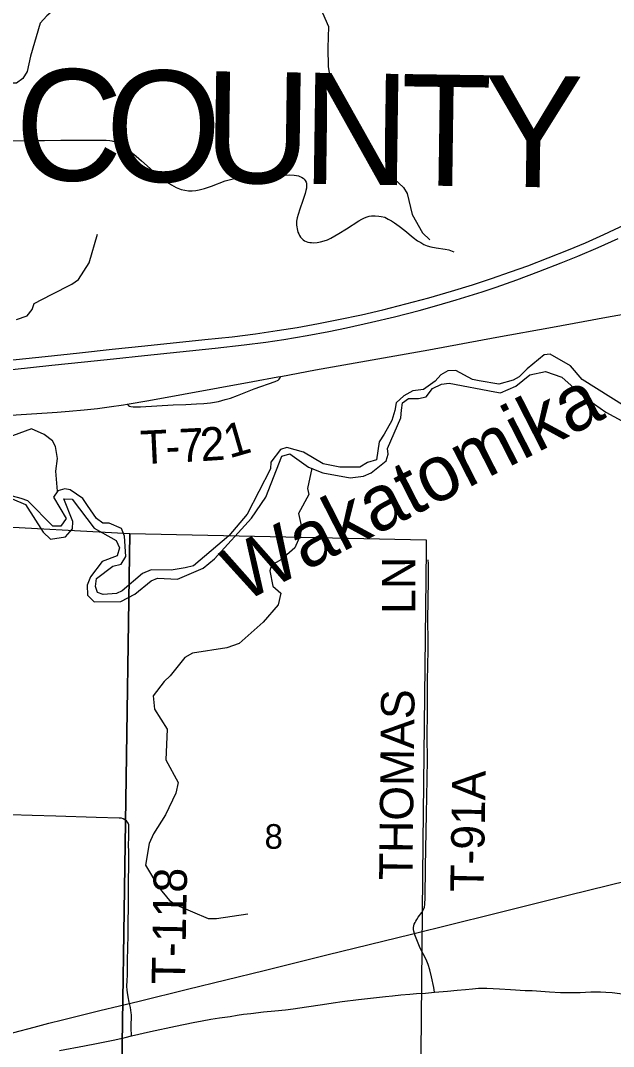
# Model space of a CAD drawing. Extents: x 0 to 34, y 0 to 22.
# Drawn here: x 3.791 to 4.8, y 14.491 to 16.238 of the extents above; entities that cross this region are included whole.
import ezdxf

# ---------------------------------------------------------------- set-up
doc = ezdxf.new("R2010")
doc.units = 0
for name, color, linetype in [('GM_X_Corporation', 7, 'Continuous'), ('GM_X_County_Road', 7, 'Continuous'), ('GM_X_County_Text', 7, 'Continuous'), ('GM_X_Minor_River', 7, 'Continuous'), ('GM_X_Minor_River_Text', 7, 'Continuous'), ('GM_X_Rail_Line', 7, 'Continuous'), ('GM_X_Section_Text', 7, 'Continuous'), ('GM_X_State_Route', 7, 'Continuous'), ('GM_X_Township_Road', 7, 'Continuous'), ('GM_X_Township_Road_Text', 7, 'Continuous')]:
    doc.layers.add(name, color=color, linetype=linetype)

msp = doc.modelspace()

# ---------------------------------------------------------------- linework, layer by layer
at = {"layer": 'GM_X_Corporation'}
for points in [[(2.9706, 15.4194), (3.9769, 15.3648), (3.9619, 14.3814), (2.9463, 14.4019)], [(3.9769, 15.3648), (4.4816, 15.354), (4.4815, 15.3372), (4.4758, 14.8389), (4.4713, 14.3604), (3.9619, 14.3814)]]:
    msp.add_lwpolyline(points, close=True, dxfattribs=at)
at = {"layer": 'GM_X_County_Road'}
for points in [[(4.2337, 15.6322), (4.2931, 15.6431), (4.4857, 15.6775), (4.6018, 15.6992), (4.6966, 15.7158), (4.7485, 15.7255), (4.7882, 15.7329), (4.8463, 15.7434), (4.9165, 15.7564), (4.9688, 15.7656)], [(3.9724, 15.5847), (4.0089, 15.5909), (4.1862, 15.6233), (4.2289, 15.6313), (4.2337, 15.6322)], [(3.3059, 15.4754), (3.3075, 15.4763), (3.3318, 15.49), (3.354, 15.501), (3.3796, 15.5123), (3.4056, 15.5223), (3.4292, 15.53), (3.4531, 15.5365), (3.4653, 15.5394), (3.4813, 15.5428), (3.4944, 15.5453), (3.5078, 15.5475), (3.5356, 15.5508), (3.5699, 15.5534), (3.6591, 15.5589), (3.8362, 15.5703), (3.8532, 15.5715), (3.8734, 15.573), (3.8993, 15.5755), (3.9215, 15.5778), (3.9414, 15.5802), (3.966, 15.5837), (3.9724, 15.5847)], [(4.4957, 14.5837), (4.5177, 14.5854), (4.5343, 14.5869), (4.5484, 14.5883), (4.5601, 14.5896), (4.5703, 14.5904), (4.5849, 14.5905), (4.6065, 14.5894), (4.6251, 14.5883), (4.6498, 14.5868), (4.6619, 14.5864), (4.6916, 14.5843), (4.7103, 14.5834), (4.7239, 14.5831), (4.7363, 14.5834), (4.7437, 14.5834), (4.7618, 14.5843), (4.7783, 14.5843), (4.7875, 14.584), (4.7978, 14.583), (4.8371, 14.5782)], [(3.9795, 14.5092), (4.012, 14.5166), (4.0544, 14.526), (4.0848, 14.532), (4.0998, 14.5348), (4.1147, 14.5377), (4.1296, 14.54), (4.1479, 14.5424), (4.1597, 14.5443), (4.1705, 14.5461), (4.183, 14.5476), (4.2045, 14.55), (4.2237, 14.5518), (4.2417, 14.5538), (4.2549, 14.5555), (4.2775, 14.5585), (4.3051, 14.5628), (4.3233, 14.5657), (4.3384, 14.5678), (4.3661, 14.571), (4.412, 14.5763), (4.4242, 14.5777), (4.4384, 14.5791), (4.4536, 14.5804), (4.4648, 14.5814), (4.4802, 14.5823), (4.4957, 14.5837)], [(3.8571, 14.4846), (3.8999, 14.4925), (3.92, 14.4965), (3.9512, 14.5027), (3.969, 14.5068), (3.9795, 14.5092)]]:
    msp.add_lwpolyline(points, dxfattribs=at)
at = {"layer": 'GM_X_Minor_River'}
for points in [[(3.9737, 16.3586), (3.9672, 16.3431), (3.9366, 16.3195), (3.9114, 16.2986), (3.8574, 16.265), (3.8355, 16.2459), (3.8242, 16.2334), (3.8078, 16.1772), (3.8019, 16.1514), (3.7947, 16.1392), (3.7838, 16.1316), (3.7626, 16.1315), (3.7271, 16.1173), (3.7142, 16.1177), (3.6823, 16.1327)], [(4.3024, 16.3549), (4.2985, 16.3224), (4.2865, 16.2904), (4.2881, 16.2757), (4.3049, 16.2514), (4.3148, 16.228), (4.3138, 16.1919), (4.3143, 16.1593), (4.3198, 16.1293), (4.3541, 16.0631), (4.385, 16.0173), (4.4044, 15.9897), (4.4428, 15.9538), (4.4489, 15.9436), (4.4574, 15.9076), (4.4753, 15.8769), (4.4875, 15.8648)], [(3.784, 15.7291), (3.8021, 15.7356), (3.8104, 15.7459), (3.8142, 15.7561), (3.8432, 15.7718), (3.878, 15.789), (3.8893, 15.797), (3.9074, 15.8255), (3.9215, 15.8741)], [(4.8203, 15.5811), (4.747, 15.6267), (4.7273, 15.6502), (4.6923, 15.6698), (4.6821, 15.669), (4.6535, 15.645), (4.6395, 15.6313), (4.6297, 15.6259), (4.6049, 15.6192), (4.5714, 15.6246), (4.5604, 15.6268), (4.5316, 15.6423), (4.5183, 15.6415), (4.5063, 15.635), (4.4965, 15.6239), (4.4768, 15.6098), (4.4587, 15.6075), (4.4432, 15.5991), (4.4304, 15.5873), (4.4282, 15.574), (4.4231, 15.557), (4.4098, 15.5341), (4.4015, 15.5208), (4.3967, 15.4902), (4.3816, 15.4854), (4.3685, 15.4779), (4.3345, 15.4779), (4.3059, 15.4833), (4.2725, 15.5033), (4.2441, 15.5111), (4.2331, 15.508), (4.2169, 15.486), (4.2162, 15.475), (4.1768, 15.3978), (4.1452, 15.3609), (4.0852, 15.3099), (4.0712, 15.306), (4.047, 15.3021), (4.0129, 15.3031), (3.9982, 15.2966), (3.9639, 15.2673), (3.9541, 15.2623), (3.9314, 15.2607), (3.9215, 15.2641), (3.9181, 15.2743), (3.9199, 15.288), (3.9478, 15.309), (3.9622, 15.3124), (3.9701, 15.3254), (3.968, 15.3599), (3.9627, 15.3731), (3.9418, 15.3822), (3.9308, 15.3825), (3.9202, 15.3904), (3.9046, 15.4124), (3.8966, 15.4245), (3.8753, 15.4392), (3.8659, 15.4407), (3.8541, 15.4376), (3.847, 15.4266), (3.8684, 15.3902), (3.8593, 15.3769), (3.8457, 15.3773), (3.8031, 15.4203), (3.7917, 15.4245), (3.7686, 15.4308)], [(3.7766, 15.4237), (3.7994, 15.4143), (3.8291, 15.367), (3.842, 15.3549), (3.8674, 15.3591), (3.8794, 15.3724), (3.8797, 15.385), (3.8644, 15.424), (3.8784, 15.4229), (3.9161, 15.3737), (3.9533, 15.3526), (3.959, 15.3401), (3.9553, 15.3264), (3.9296, 15.3172), (3.91, 15.291), (3.9044, 15.2769), (3.9049, 15.2599), (3.9159, 15.2485), (3.9617, 15.2487), (3.9851, 15.2613), (4.013, 15.2842), (4.024, 15.2888), (4.0581, 15.287), (4.1015, 15.3054), (4.1207, 15.3217), (4.184, 15.3906), (4.2085, 15.4264), (4.2358, 15.4963), (4.249, 15.5005), (4.2813, 15.4779), (4.3052, 15.4681), (4.3518, 15.4595), (4.3749, 15.4623), (4.3877, 15.468), (4.413, 15.4886), (4.4164, 15.4996), (4.4156, 15.5095), (4.4381, 15.5615), (4.4391, 15.5748), (4.441, 15.5873), (4.4514, 15.5947), (4.4683, 15.5947), (4.4811, 15.5973), (4.4923, 15.6118), (4.5075, 15.619), (4.5207, 15.6206), (4.598, 15.6061), (4.6078, 15.6042), (4.6339, 15.6157), (4.658, 15.6348), (4.6845, 15.6405), (4.7122, 15.6308), (4.7487, 15.5987), (4.787, 15.5715), (4.8345, 15.5458)], [(3.8538, 15.437), (3.8506, 15.471), (3.8539, 15.4922), (3.8504, 15.5127), (3.8451, 15.5226), (3.831, 15.5335), (3.8094, 15.5429), (3.7769, 15.531)], [(4.2866, 15.4757), (4.2791, 15.4416), (4.2818, 15.431), (4.2642, 15.3986), (4.2684, 15.3782), (4.2674, 15.3626), (4.2576, 15.3402), (4.235, 15.3207), (4.218, 15.3108), (4.2154, 15.3013), (4.2204, 15.2748), (4.2341, 15.2631), (4.2293, 15.2433), (4.204, 15.214), (4.1629, 15.1774), (4.1421, 15.1701), (4.0837, 15.1611), (4.0705, 15.1538), (4.0453, 15.1222), (4.0351, 15.1127), (4.0166, 15.0883), (4.019, 15.0656), (4.0404, 15.0315), (4.0383, 14.9796), (4.059, 14.941), (4.0549, 14.9227), (4.0376, 14.8855), (4.0169, 14.8531), (4.0098, 14.8368), (4.0035, 14.8), (4.0261, 14.7617), (4.0444, 14.7398), (4.0569, 14.7319), (4.1104, 14.7094), (4.1241, 14.7091), (4.1779, 14.7173)]]:
    msp.add_lwpolyline(points, dxfattribs=at)
at = {"layer": 'GM_X_Rail_Line'}
msp.add_lwpolyline([(3.6972, 14.4902), (3.7191, 14.4967), (3.74, 14.5034), (3.7793, 14.5148), (3.8138, 14.5243), (3.839, 14.5311), (3.862, 14.5367), (3.9255, 14.5525), (3.9926, 14.5684), (4.075, 14.5889), (4.2057, 14.6209), (4.3124, 14.6473), (4.4566, 14.6827), (4.5938, 14.7167), (4.7232, 14.7487), (4.8596, 14.7823)], dxfattribs=at)
at = {"layer": 'GM_X_State_Route'}
for points in [[(3.7061, 15.653), (3.8327, 15.6663), (3.8914, 15.6724), (3.947, 15.6783), (4.0026, 15.6843), (4.1045, 15.6948), (4.1509, 15.6998), (4.191, 15.7049), (4.2279, 15.7103), (4.2616, 15.7157), (4.2983, 15.7223), (4.3319, 15.7288), (4.3714, 15.7372), (4.4077, 15.7457), (4.4468, 15.7557), (4.4858, 15.7662), (4.5246, 15.7774), (4.5602, 15.7883), (4.5927, 15.7989), (4.6251, 15.81), (4.6542, 15.8207), (4.689, 15.8341), (4.7237, 15.8478), (4.7524, 15.8598), (4.7836, 15.8736), (4.8203, 15.8906)], [(3.7762, 15.6437), (3.8441, 15.6511), (3.8997, 15.6569), (3.9491, 15.6623), (4.0016, 15.6679), (4.1221, 15.6804), (4.1715, 15.6859), (4.2085, 15.6907), (4.2392, 15.6953), (4.279, 15.7019), (4.3156, 15.7086), (4.346, 15.7148), (4.3884, 15.7243), (4.4277, 15.7336), (4.4697, 15.7446), (4.4997, 15.7528), (4.5324, 15.7625), (4.5768, 15.7764), (4.6004, 15.7843), (4.6355, 15.7966), (4.6734, 15.8107), (4.711, 15.8253), (4.7398, 15.837), (4.774, 15.8517), (4.808, 15.8668)]]:
    msp.add_lwpolyline(points, dxfattribs=at)
at = {"layer": 'GM_X_Township_Road'}
for points in [[(3.7755, 16.0333), (3.7973, 16.0336), (3.8159, 16.0339), (3.8314, 16.0341), (3.8592, 16.0346), (3.8747, 16.0345), (3.8964, 16.0346), (3.9306, 16.0347), (3.9368, 16.0344), (3.9429, 16.0336), (3.946, 16.0331), (3.9519, 16.0314), (3.9577, 16.029), (3.9631, 16.0261), (3.9682, 16.0227), (3.9756, 16.0171), (3.9874, 16.0073), (3.9968, 15.9991), (4.0061, 15.9909), (4.0225, 15.9768), (4.0322, 15.969), (4.0398, 15.9636), (4.0441, 15.9607)], [(4.0441, 15.9607), (4.0476, 15.9585), (4.0557, 15.9539), (4.0614, 15.9515), (4.0644, 15.9505), (4.0704, 15.9491), (4.0766, 15.9484), (4.0828, 15.9484), (4.089, 15.9489), (4.0951, 15.9499), (4.1041, 15.9523), (4.1159, 15.9562), (4.1392, 15.9649), (4.148, 15.9677), (4.1571, 15.9699), (4.1663, 15.9714), (4.1786, 15.9724), (4.2158, 15.974), (4.2388, 15.975), (4.2487, 15.9755), (4.2568, 15.9749), (4.2608, 15.9743), (4.2638, 15.9736), (4.2665, 15.9725), (4.2692, 15.9715), (4.2717, 15.9699), (4.2739, 15.9681), (4.2756, 15.9657), (4.2769, 15.9629), (4.2774, 15.9611), (4.2776, 15.9593), (4.2778, 15.9556), (4.2774, 15.9527), (4.2765, 15.9489), (4.2751, 15.9434), (4.2711, 15.9316), (4.266, 15.9169), (4.2632, 15.9081), (4.2617, 15.902), (4.2607, 15.8964), (4.2607, 15.8928), (4.2607, 15.8897), (4.261, 15.8866), (4.2615, 15.8836), (4.2622, 15.8805), (4.2631, 15.8775), (4.2643, 15.8747), (4.2657, 15.8719), (4.2674, 15.8693), (4.2694, 15.867), (4.2718, 15.8649), (4.2743, 15.8632), (4.2771, 15.8619), (4.28, 15.8609), (4.2831, 15.8602), (4.2862, 15.8599), (4.2893, 15.8598), (4.2955, 15.8601), (4.3016, 15.8612), (4.3076, 15.8628), (4.3134, 15.865), (4.319, 15.8677), (4.3324, 15.8755), (4.3456, 15.8837), (4.3666, 15.8969), (4.372, 15.9), (4.3766, 15.9023), (4.3807, 15.9039), (4.3844, 15.905), (4.3885, 15.9056), (4.3943, 15.9056), (4.4005, 15.9053), (4.4048, 15.9047), (4.4112, 15.9031), (4.4169, 15.8999), (4.4224, 15.897), (4.4277, 15.8937), (4.4352, 15.8882), (4.4449, 15.8805), (4.4593, 15.8687), (4.4668, 15.8632), (4.4721, 15.8599), (4.4776, 15.857), (4.4833, 15.8547), (4.4893, 15.853), (4.4984, 15.8513), (4.5138, 15.8489), (4.5199, 15.8476), (4.5228, 15.8467), (4.5257, 15.8456), (4.5285, 15.8443)], [(3.9724, 15.5847), (3.9743, 15.5825), (3.9761, 15.5814), (3.9784, 15.581), (3.9823, 15.5805), (3.9887, 15.5801), (3.9949, 15.5803), (4.0504, 15.5839), (4.0721, 15.5845), (4.0906, 15.5853), (4.1029, 15.5862), (4.1143, 15.5872), (4.1212, 15.5881), (4.1276, 15.5893), (4.1394, 15.5926), (4.1483, 15.5953), (4.16, 15.5995), (4.1886, 15.611), (4.2241, 15.6233), (4.2296, 15.6259), (4.2311, 15.6272), (4.2323, 15.629), (4.2337, 15.6322)], [(4.4957, 14.5837), (4.4942, 14.5917), (4.4907, 14.6096), (4.4878, 14.6217), (4.485, 14.6306), (4.4812, 14.6391), (4.4714, 14.6585), (4.4654, 14.6728), (4.4621, 14.6815), (4.4604, 14.6875), (4.46, 14.6905), (4.46, 14.6936), (4.4604, 14.6967), (4.461, 14.6995), (4.4624, 14.7025), (4.4636, 14.7049), (4.4654, 14.7076), (4.4678, 14.7112), (4.4739, 14.7194), (4.4752, 14.7214), (4.4763, 14.7231), (4.4776, 14.7259), (4.4784, 14.7283), (4.4788, 14.7298), (4.4791, 14.7316), (4.4793, 14.7338), (4.4797, 14.7443), (4.4803, 14.7971), (4.4817, 14.8873), (4.4832, 14.9463), (4.4835, 14.9805), (4.4828, 15.0178), (4.4836, 15.0613), (4.4837, 15.0967), (4.4838, 15.1141), (4.4849, 15.1659), (4.4848, 15.1762), (4.4847, 15.1918), (4.4843, 15.2077), (4.4843, 15.2178), (4.4853, 15.285), (4.4853, 15.3037), (4.4853, 15.3094), (4.4853, 15.3129), (4.485, 15.3198)], [(3.9795, 14.5092), (3.9794, 14.5117), (3.9789, 14.5206), (3.9792, 14.5299), (3.9796, 14.5392), (3.9795, 14.5454), (3.9791, 14.5485), (3.9777, 14.5576), (3.9758, 14.5668), (3.9742, 14.5755), (3.9729, 14.5829), (3.9723, 14.5873), (3.9719, 14.5942), (3.9723, 14.6035), (3.9727, 14.6128), (3.9727, 14.6252), (3.9731, 14.6376), (3.9738, 14.681), (3.9751, 14.8207), (3.9748, 14.8361), (3.975, 14.8454), (3.9751, 14.8641), (3.975, 14.8671), (3.9749, 14.8689), (3.9745, 14.8701), (3.9738, 14.8717), (3.973, 14.873), (3.971, 14.8754), (3.9685, 14.8774), (3.9657, 14.8789), (3.9628, 14.8798), (3.9589, 14.8801), (3.9194, 14.8811), (3.8511, 14.8832), (3.8108, 14.8846), (3.7735, 14.8858)]]:
    msp.add_lwpolyline(points, dxfattribs=at)

# ---------------------------------------------------------------- texts
at = {"layer": 'GM_X_County_Text'}
for s, rotation, p in [('C', 359.1883, (3.7801, 15.967)), ('O', 359.1883, (3.9343, 15.9648)), ('U', 359.1877, (4.1017, 15.9625)), ('N', 359.1883, (4.2692, 15.9601)), ('T', 359.1887, (4.4367, 15.9577)), ('Y', 359.1883, (4.5784, 15.9557))]:
    msp.add_text(s, height=0.1894, rotation=rotation, dxfattribs=at).set_placement(p)
at = {"layer": 'GM_X_Minor_River_Text'}
msp.add_text('Wakatomika', height=0.0947, rotation=27.0325, dxfattribs=at).set_placement((4.1688, 15.2461))
at = {"layer": 'GM_X_Section_Text'}
msp.add_text('8', height=0.0419, rotation=0, dxfattribs=at).set_placement((4.2062, 14.8279))
at = {"layer": 'GM_X_Township_Road_Text'}
for s, height, rotation, p in [('1', 0.0568, 16.1648, (4.1462, 15.4923)), ('T', 0.0568, 2.761, (3.9963, 15.4827)), ('7', 0.0568, 2.8512, (4.0621, 15.4859)), ('2', 0.0568, 3.8889, (4.0982, 15.4877)), ('-', 0.0568, 2.7792, (4.0387, 15.4847)), ('LN', 0.05682, 90, (4.463, 15.2279)), ('THOMAS', 0.05682, 89.3516, (4.458, 14.7741)), ('T-91A', 0.05682, 88.9695, (4.5791, 14.754)), ('T-118', 0.05682, 88.9027, (4.0706, 14.5966))]:
    msp.add_text(s, height=height, rotation=rotation, dxfattribs=at).set_placement(p)

doc.saveas('drawing.dxf')
